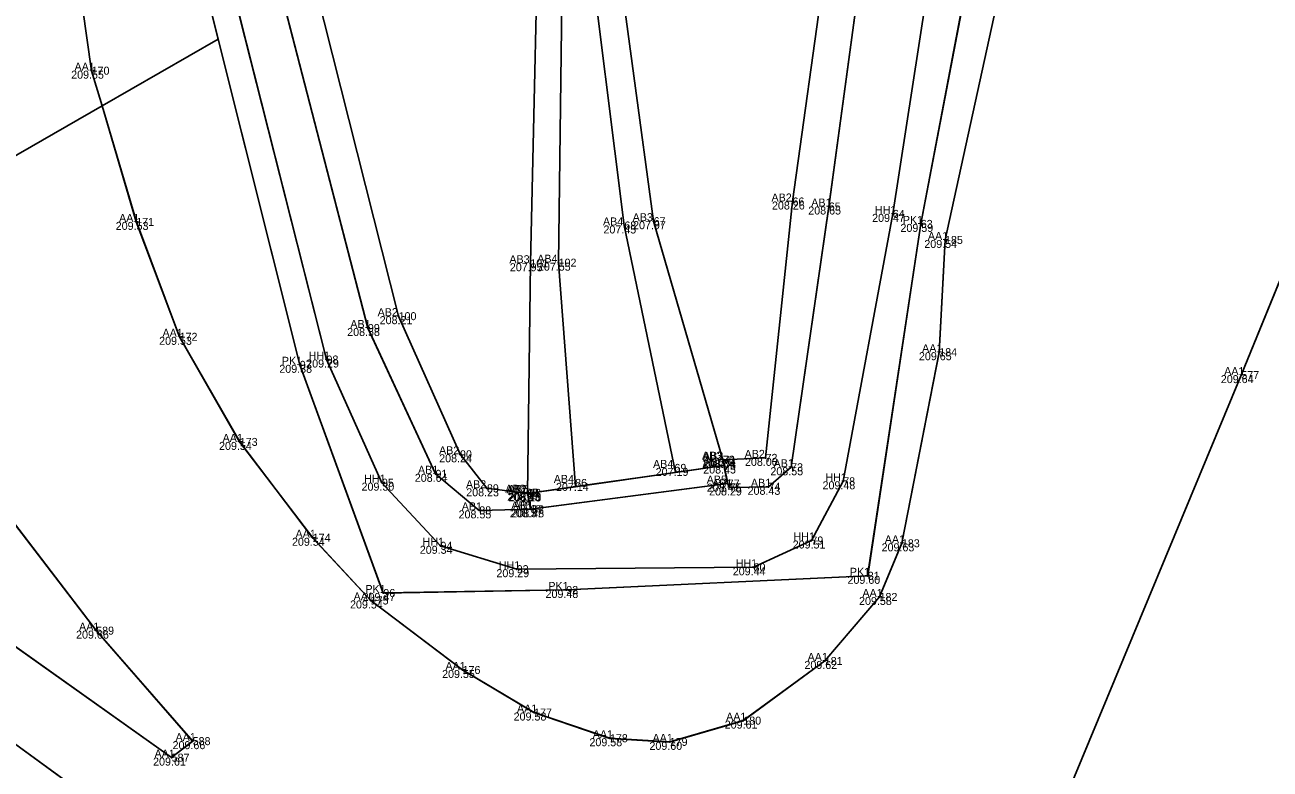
# Model space of a CAD drawing. Extents: x -262982 to -262706, y -1238714 to -1237093.
# Drawn here: x -262957.98 to -262926.85, y -1238394.45 to -1238375.85 of the extents above; entities that cross this region are included whole.
import ezdxf

# ---------------------------------------------------------------- set-up
doc = ezdxf.new("R2010")
doc.units = 0
for name, color, linetype in [('01_Hrana_betónu', 7, 'Continuous'), ('02_Oplotenie', 7, 'Continuous'), ('03_Asfalt', 7, 'Continuous'), ('05_Hrana_terénu', 7, 'Continuous'), ('07_Iné', 7, 'Continuous'), ('10', 7, 'Continuous'), ('Groma (21)', 7, 'Continuous'), ('Groma (22)', 7, 'Continuous'), ('Groma (23)', 7, 'Continuous'), ('Groma (24)', 7, 'Continuous'), ('U001_Zeleň_mimo', 7, 'Continuous'), ('U002_Asfalt', 7, 'Continuous'), ('U002_Betónové panely', 7, 'Continuous'), ('U002_Betóny_prídavné', 7, 'Continuous'), ('U002_Zeleň_mimo', 7, 'Continuous'), ('U002_Zeleň_vnútro', 7, 'Continuous'), ('U002_Zeleň_zatrávňovač', 7, 'Continuous')]:
    doc.layers.add(name, color=color, linetype=linetype)

msp = doc.modelspace()

# ---------------------------------------------------------------- linework, layer by layer
at = {"layer": '01_Hrana_betónu'}
for points in [[(-262944.213, -1238387.387), (-262944.634, -1238381.789), (-262944.5, -1238371.343), (-262941.2, -1238360.927), (-262935.086, -1238341.218), (-262927.632, -1238317.179), (-262920.793, -1238295.265), (-262911.171, -1238262.813), (-262915.352, -1238261.064), (-262915.337, -1238259.329), (-262909.866, -1238261.629), (-262904.904, -1238263.716)], [(-262916.095, -1238261.519), (-262911.974, -1238263.293), (-262921.591, -1238294.909), (-262928.534, -1238317.073), (-262935.896, -1238340.99), (-262941.971, -1238360.685), (-262945.096, -1238371.115), (-262945.34, -1238381.803), (-262945.412, -1238387.557)], [(-262941.714, -1238387.032), (-262942.991, -1238380.859), (-262943.934, -1238373.35), (-262940.485, -1238361.041), (-262934.456, -1238341.421), (-262927.277, -1238318.134), (-262920.116, -1238294.802), (-262913.64, -1238273.614), (-262910.214, -1238263.245), (-262905.769, -1238265.099), (-262904.904, -1238263.716)], [(-262905.769, -1238265.099), (-262909.81, -1238264.181), (-262912.956, -1238273.861), (-262919.396, -1238295.066), (-262926.538, -1238318.409), (-262933.693, -1238341.579), (-262939.683, -1238361.151), (-262943.246, -1238373.477), (-262942.259, -1238380.752), (-262940.526, -1238386.713)], [(-262905.769, -1238265.099), (-262909.014, -1238275.12), (-262915.393, -1238296.189), (-262922.597, -1238319.497), (-262929.796, -1238342.936), (-262935.083, -1238362.17), (-262937.995, -1238374.567), (-262938.788, -1238380.26), (-262939.46, -1238386.668), (-262940.526, -1238386.713), (-262940.498, -1238386.859)], [(-262940.36, -1238387.407), (-262939.388, -1238387.391), (-262938.822, -1238386.902), (-262937.88, -1238380.385), (-262937.119, -1238374.802), (-262934.23, -1238362.39), (-262928.952, -1238343.2), (-262921.717, -1238319.813), (-262915.107, -1238298.192), (-262908.208, -1238275.423), (-262904.855, -1238265.436)], [(-262945.333, -1238387.95), (-262946.617, -1238387.98), (-262947.712, -1238387.066), (-262949.402, -1238383.422), (-262952.187, -1238372.656), (-262952.759, -1238366.382)], [(-262951.91, -1238366.581), (-262951.321, -1238372.499), (-262948.634, -1238383.126), (-262947.098, -1238386.578), (-262946.426, -1238387.428), (-262945.412, -1238387.557)], [(-262945.333, -1238387.95), (-262945.412, -1238387.557), (-262944.213, -1238387.387), (-262941.714, -1238387.032), (-262940.498, -1238386.859), (-262940.407, -1238387.311), (-262940.36, -1238387.407)]]:
    msp.add_lwpolyline(points, dxfattribs=at)
at = {"layer": '02_Oplotenie'}
msp.add_lwpolyline([(-262939.39, -1238320.83), (-262941.19, -1238324.79), (-262946.68, -1238336.9), (-262951.035, -1238350.68), (-262953.195, -1238358.97), (-262953.815, -1238358.809), (-262955.312, -1238364.513), (-262954.553, -1238364.724), (-262954.681, -1238366.785), (-262954.024, -1238372.698), (-262953.142, -1238376.2), (-262951.104, -1238384.342), (-262949.016, -1238390.045), (-262944.443, -1238389.969), (-262936.906, -1238389.616), (-262935.581, -1238380.82), (-262934.566, -1238375.513), (-262931.812, -1238363.194), (-262926.159, -1238344.076), (-262918.903, -1238320.384), (-262912.242, -1238298.942), (-262905.326, -1238276.054), (-262902.598, -1238266.292), (-262902.107, -1238264.892)], dxfattribs=at)
at = {"layer": '03_Asfalt'}
for points in [[(-262929.61, -1238361.054), (-262931.199, -1238364.162), (-262933.003, -1238372.216), (-262934.974, -1238381.221), (-262935.119, -1238384.027), (-262936.052, -1238388.803), (-262936.611, -1238390.144), (-262937.981, -1238391.744), (-262940.017, -1238393.235), (-262941.857, -1238393.766), (-262943.351, -1238393.675), (-262945.246, -1238393.033), (-262947.034, -1238391.969), (-262949.331, -1238390.232), (-262950.782, -1238388.665), (-262952.605, -1238386.269), (-262954.108, -1238383.642), (-262955.193, -1238380.77), (-262956.048, -1238377.869), (-262956.307, -1238376.99), (-262956.874, -1238372.978), (-262956.554, -1238367.788), (-262955.999, -1238364.917), (-262954.725, -1238360.416)], [(-262931.78, -1238394.73), (-262927.567, -1238384.599), (-262924.973, -1238378.239), (-262922.576, -1238372.621), (-262920.572, -1238369.785), (-262920.498, -1238369.428)], [(-262967.893, -1238384.386), (-262961.125, -1238389.323), (-262954.307, -1238394.16), (-262953.782, -1238393.748), (-262956.194, -1238390.986), (-262959.165, -1238387.112), (-262961.145, -1238384.138), (-262962.629, -1238381.652), (-262966.72, -1238383.885)], [(-262954.673, -1238396.412), (-262962.054, -1238391.026), (-262968.907, -1238386.238), (-262974.83, -1238389.493)]]:
    msp.add_lwpolyline(points, dxfattribs=at)
at = {"layer": '05_Hrana_terénu'}
msp.add_lwpolyline([(-262920.126, -1238320.151), (-262927.385, -1238343.686), (-262932.704, -1238362.854), (-262935.453, -1238375.219), (-262936.279, -1238380.57), (-262937.519, -1238387.253), (-262938.314, -1238388.733), (-262939.759, -1238389.403), (-262945.681, -1238389.45), (-262947.587, -1238388.865), (-262949.049, -1238387.288), (-262950.436, -1238384.21), (-262953.347, -1238372.702), (-262953.777, -1238366.63), (-262954.163, -1238366.041), (-262952.487, -1238358.01), (-262951.855, -1238357.25), (-262949.897, -1238349.853), (-262950.29, -1238348.92), (-262949.45, -1238345.83), (-262948.76, -1238345.496), (-262946.63, -1238339.15), (-262945.04, -1238334.12), (-262941.75, -1238326.63)], dxfattribs=at)
at = {"layer": '07_Iné'}
msp.add_lwpolyline([(-262940.407, -1238387.311), (-262940.498, -1238386.859), (-262945.412, -1238387.557), (-262945.334, -1238387.946)], close=True, dxfattribs=at)
at = {"layer": '10'}
msp.add_lwpolyline([(-262982.434, -1238375.977), (-262968.907, -1238386.238), (-262962.054, -1238391.026), (-262954.673, -1238396.412), (-262941.774, -1238405.784), (-262928.896, -1238415.327), (-262917.716, -1238423.993), (-262905.824, -1238433.621), (-262895.067, -1238441.663), (-262870.407, -1238460.6)], dxfattribs=at)
at = {"layer": 'Groma (21)'}
for centre in [(-262956.307, -1238376.99), (-262938.788, -1238380.26), (-262937.88, -1238380.385), (-262936.279, -1238380.57), (-262955.193, -1238380.77), (-262942.991, -1238380.859), (-262942.259, -1238380.752), (-262935.581, -1238380.82), (-262934.974, -1238381.221), (-262945.34, -1238381.803), (-262944.634, -1238381.789), (-262948.634, -1238383.126), (-262949.402, -1238383.422), (-262954.108, -1238383.642), (-262935.119, -1238384.027), (-262951.104, -1238384.342), (-262950.436, -1238384.21), (-262927.567, -1238384.599), (-262952.605, -1238386.269), (-262947.098, -1238386.578), (-262940.526, -1238386.713), (-262940.499, -1238386.717), (-262940.498, -1238386.859), (-262939.46, -1238386.668), (-262938.822, -1238386.902), (-262947.712, -1238387.066), (-262941.738, -1238386.918), (-262949.049, -1238387.288), (-262946.426, -1238387.428), (-262944.22, -1238387.294), (-262940.407, -1238387.311), (-262940.36, -1238387.407), (-262939.388, -1238387.391), (-262937.519, -1238387.253), (-262945.444, -1238387.54), (-262945.412, -1238387.557), (-262945.37, -1238387.544), (-262946.617, -1238387.98), (-262945.333, -1238387.95), (-262945.294, -1238387.955), (-262950.782, -1238388.665), (-262938.314, -1238388.733), (-262947.587, -1238388.865), (-262936.052, -1238388.803), (-262939.759, -1238389.403), (-262945.681, -1238389.45), (-262936.906, -1238389.616), (-262944.443, -1238389.969), (-262949.331, -1238390.232), (-262949.016, -1238390.045), (-262936.611, -1238390.144), (-262956.194, -1238390.986), (-262937.981, -1238391.744), (-262947.034, -1238391.969), (-262945.246, -1238393.033), (-262940.017, -1238393.235), (-262953.782, -1238393.748), (-262943.351, -1238393.675), (-262941.857, -1238393.766), (-262954.307, -1238394.16)]:
    msp.add_circle(centre, 0.01, dxfattribs=at)
at = {"layer": 'U001_Zeleň_mimo'}
msp.add_lwpolyline([(-262966.43, -1238405.69), (-262974.83, -1238389.49), (-262968.91, -1238386.24), (-262962.05, -1238391.03), (-262954.67, -1238396.41)], dxfattribs=at)
msp.add_lwpolyline([(-262966.43, -1238405.69), (-262974.83, -1238389.49), (-262968.91, -1238386.24), (-262962.05, -1238391.03), (-262954.67, -1238396.41)], dxfattribs=at)
at = {"layer": 'U002_Asfalt'}
for points in [[(-262926.72, -1238350.73), (-262915.49, -1238369.52), (-262916.65, -1238369.25), (-262918.3, -1238369.33), (-262920.5, -1238369.43), (-262920.57, -1238369.78), (-262922.58, -1238372.62), (-262924.97, -1238378.24), (-262927.57, -1238384.6), (-262931.78, -1238394.73)], [(-262962.63, -1238381.65), (-262956.048, -1238377.869), (-262955.19, -1238380.77), (-262954.11, -1238383.64), (-262952.61, -1238386.27), (-262950.78, -1238388.67), (-262949.33, -1238390.23), (-262947.03, -1238391.97), (-262945.25, -1238393.03), (-262943.35, -1238393.68), (-262941.86, -1238393.77), (-262940.02, -1238393.24), (-262937.98, -1238391.74), (-262936.61, -1238390.14), (-262936.05, -1238388.8), (-262935.12, -1238384.03), (-262934.97, -1238381.22), (-262933, -1238372.22), (-262931.2, -1238364.16), (-262929.61, -1238361.05)], [(-262961.13, -1238389.32), (-262954.31, -1238394.16), (-262953.78, -1238393.75), (-262956.19, -1238390.99), (-262959.16, -1238387.11)], [(-262954.67, -1238396.41), (-262962.05, -1238391.03)]]:
    msp.add_lwpolyline(points, dxfattribs=at)
at = {"layer": 'U002_Betónové panely'}
msp.add_lwpolyline([(-262928.95, -1238343.2), (-262934.23, -1238362.39), (-262937.12, -1238374.8), (-262937.88, -1238380.39), (-262938.82, -1238386.9), (-262939.39, -1238387.39), (-262940.36, -1238387.41), (-262940.41, -1238387.31), (-262940.5, -1238386.86), (-262941.71, -1238387.03), (-262944.21, -1238387.39), (-262945.41, -1238387.56), (-262945.33, -1238387.95), (-262946.62, -1238387.98), (-262947.71, -1238387.07), (-262949.4, -1238383.42), (-262952.19, -1238372.66), (-262952.76, -1238366.38), (-262951.91, -1238366.58), (-262950.1, -1238358.54)], dxfattribs=at)
at = {"layer": 'U002_Betóny_prídavné'}
msp.add_lwpolyline([(-262940.5, -1238386.86), (-262940.41, -1238387.31), (-262945.33, -1238387.95), (-262945.41, -1238387.56)], close=True, dxfattribs=at)
at = {"layer": 'U002_Zeleň_mimo'}
for points in [[(-262931.78, -1238394.73), (-262927.57, -1238384.6), (-262924.97, -1238378.24), (-262922.58, -1238372.62), (-262920.5, -1238369.43), (-262918.3, -1238369.33), (-262916.65, -1238369.25), (-262915.49, -1238369.52), (-262914.76, -1238370.7), (-262914.55, -1238372.02), (-262914.27, -1238382.69), (-262914.16, -1238387.19), (-262913.44, -1238391.68), (-262911.99, -1238397.34)], [(-262933, -1238372.22), (-262934.97, -1238381.22), (-262935.12, -1238384.03), (-262936.05, -1238388.8), (-262936.61, -1238390.14), (-262937.98, -1238391.74), (-262940.02, -1238393.24), (-262941.86, -1238393.77), (-262943.35, -1238393.68), (-262945.25, -1238393.03), (-262947.03, -1238391.97), (-262949.33, -1238390.23), (-262950.78, -1238388.67), (-262952.61, -1238386.27), (-262954.11, -1238383.64), (-262955.19, -1238380.77), (-262956.048, -1238377.869), (-262953.142, -1238376.2), (-262951.1, -1238384.34), (-262949.02, -1238390.05), (-262944.44, -1238389.97), (-262936.91, -1238389.62), (-262935.58, -1238380.82), (-262934.57, -1238375.51)]]:
    msp.add_lwpolyline(points, dxfattribs=at)
msp.add_lwpolyline([(-262961.15, -1238384.14), (-262959.16, -1238387.11), (-262956.19, -1238390.99), (-262953.78, -1238393.75), (-262954.31, -1238394.16), (-262961.13, -1238389.32), (-262967.89, -1238384.39), (-262966.72, -1238383.89), (-262962.63, -1238381.65)], close=True, dxfattribs=at)
at = {"layer": 'U002_Zeleň_vnútro'}
for points in [[(-262918.9, -1238320.38), (-262926.16, -1238344.08), (-262931.81, -1238363.19), (-262934.57, -1238375.51), (-262935.58, -1238380.82), (-262936.91, -1238389.62), (-262944.44, -1238389.97), (-262949.02, -1238390.05), (-262951.1, -1238384.34), (-262954.02, -1238372.7), (-262954.68, -1238366.78), (-262954.55, -1238364.72), (-262953.2, -1238358.97), (-262951.03, -1238350.68), (-262946.68, -1238336.9), (-262941.19, -1238324.79)], [(-262952.49, -1238358.01), (-262954.16, -1238366.04), (-262953.78, -1238366.63), (-262953.35, -1238372.7), (-262950.44, -1238384.21), (-262949.05, -1238387.29), (-262947.59, -1238388.87), (-262945.68, -1238389.45), (-262939.76, -1238389.4), (-262938.31, -1238388.73), (-262937.52, -1238387.25), (-262936.28, -1238380.57), (-262935.45, -1238375.22), (-262932.7, -1238362.85), (-262927.39, -1238343.69)]]:
    msp.add_lwpolyline(points, dxfattribs=at)
at = {"layer": 'U002_Zeleň_zatrávňovač'}
for points in [[(-262935.45, -1238375.22), (-262936.28, -1238380.57), (-262937.52, -1238387.25), (-262938.31, -1238388.73), (-262939.76, -1238389.4), (-262945.68, -1238389.45), (-262947.59, -1238388.87), (-262949.05, -1238387.29), (-262950.44, -1238384.21), (-262953.35, -1238372.7)], [(-262952.19, -1238372.66), (-262949.4, -1238383.42), (-262947.71, -1238387.07), (-262946.62, -1238387.98), (-262945.33, -1238387.95), (-262940.41, -1238387.31), (-262940.36, -1238387.41), (-262939.39, -1238387.39), (-262938.82, -1238386.9), (-262937.88, -1238380.39), (-262937.12, -1238374.8)]]:
    msp.add_lwpolyline(points, dxfattribs=at)

# ---------------------------------------------------------------- texts
at = {"layer": 'Groma (22)'}
for s, p in [('170', (-262956.307, -1238377.09)), ('66', (-262938.788, -1238380.36)), ('65', (-262937.88, -1238380.485)), ('171', (-262955.193, -1238380.87)), ('67', (-262942.259, -1238380.852)), ('64', (-262936.279, -1238380.67)), ('68', (-262942.991, -1238380.959)), ('63', (-262935.581, -1238380.92)), ('185', (-262934.974, -1238381.321)), ('101', (-262945.34, -1238381.903)), ('102', (-262944.634, -1238381.889)), ('100', (-262948.634, -1238383.226)), ('99', (-262949.402, -1238383.522)), ('172', (-262954.108, -1238383.742)), ('184', (-262935.119, -1238384.127)), ('97', (-262951.104, -1238384.442)), ('98', (-262950.436, -1238384.31)), ('577', (-262927.567, -1238384.699)), ('173', (-262952.605, -1238386.369)), ('90', (-262947.098, -1238386.678)), ('72', (-262939.46, -1238386.768)), ('69', (-262941.738, -1238387.018)), ('70', (-262940.526, -1238386.813)), ('71', (-262940.499, -1238386.817)), ('76', (-262940.498, -1238386.959)), ('73', (-262938.822, -1238387.002)), ('95', (-262949.049, -1238387.388)), ('91', (-262947.712, -1238387.166)), ('86', (-262944.22, -1238387.394)), ('77', (-262940.407, -1238387.411)), ('78', (-262937.519, -1238387.353)), ('89', (-262946.426, -1238387.528)), ('85', (-262945.444, -1238387.64)), ('84', (-262945.412, -1238387.657)), ('83', (-262945.37, -1238387.644)), ('75', (-262940.36, -1238387.507)), ('74', (-262939.388, -1238387.491)), ('88', (-262946.617, -1238388.08)), ('87', (-262945.333, -1238388.05)), ('82', (-262945.294, -1238388.055)), ('174', (-262950.782, -1238388.765)), ('94', (-262947.587, -1238388.965)), ('79', (-262938.314, -1238388.833)), ('183', (-262936.052, -1238388.903)), ('93', (-262945.681, -1238389.55)), ('80', (-262939.759, -1238389.503)), ('81', (-262936.906, -1238389.716)), ('96', (-262949.016, -1238390.145)), ('92', (-262944.443, -1238390.069)), ('175', (-262949.331, -1238390.332)), ('182', (-262936.611, -1238390.244)), ('589', (-262956.194, -1238391.086)), ('176', (-262947.034, -1238392.069)), ('181', (-262937.981, -1238391.844)), ('177', (-262945.246, -1238393.133)), ('180', (-262940.017, -1238393.335)), ('588', (-262953.782, -1238393.848)), ('178', (-262943.351, -1238393.775)), ('179', (-262941.857, -1238393.866)), ('587', (-262954.307, -1238394.26))]:
    msp.add_text(s, height=0.2, dxfattribs=at).set_placement(p)
at = {"layer": 'Groma (23)'}
for s, p in [('209.55', (-262956.819, -1238377.19)), ('208.26', (-262939.3, -1238380.46)), ('208.65', (-262938.392, -1238380.585)), ('209.47', (-262936.796, -1238380.77)), ('209.53', (-262955.705, -1238380.97)), ('207.45', (-262943.513, -1238381.059)), ('207.97', (-262942.772, -1238380.952)), ('209.59', (-262936.088, -1238381.02)), ('209.54', (-262935.491, -1238381.421)), ('207.95', (-262945.853, -1238382.003)), ('207.55', (-262945.151, -1238381.989)), ('208.21', (-262949.107, -1238383.326)), ('208.58', (-262949.919, -1238383.622)), ('209.53', (-262954.62, -1238383.842)), ('209.65', (-262935.626, -1238384.227)), ('209.38', (-262951.616, -1238384.542)), ('209.29', (-262950.943, -1238384.41)), ('209.64', (-262928.079, -1238384.799)), ('209.54', (-262953.122, -1238386.469)), ('208.24', (-262947.619, -1238386.778)), ('208.04', (-262941.046, -1238386.913)), ('208.04', (-262941.019, -1238386.917)), ('208.45', (-262941.019, -1238387.059)), ('208.00', (-262939.975, -1238386.868)), ('208.55', (-262939.339, -1238387.102)), ('208.64', (-262948.229, -1238387.266)), ('207.19', (-262942.207, -1238387.118)), ('209.30', (-262949.56, -1238387.488)), ('208.23', (-262946.943, -1238387.628)), ('207.14', (-262944.699, -1238387.494)), ('208.47', (-262940.929, -1238387.511)), ('208.29', (-262940.872, -1238387.607)), ('208.43', (-262939.909, -1238387.591)), ('209.48', (-262938.036, -1238387.453)), ('208.13', (-262945.917, -1238387.74)), ('208.40', (-262945.89, -1238387.744)), ('208.15', (-262945.885, -1238387.757)), ('208.55', (-262947.134, -1238388.18)), ('208.37', (-262945.85, -1238388.15)), ('208.43', (-262945.815, -1238388.155)), ('209.54', (-262951.299, -1238388.865)), ('209.51', (-262938.782, -1238388.933)), ('209.34', (-262948.104, -1238389.065)), ('209.63', (-262936.559, -1238389.003)), ('209.29', (-262946.188, -1238389.65)), ('209.44', (-262940.28, -1238389.603)), ('209.60', (-262937.412, -1238389.816)), ('209.48', (-262944.96, -1238390.169)), ('209.54', (-262949.848, -1238390.432)), ('209.47', (-262949.533, -1238390.245)), ('209.58', (-262937.123, -1238390.344)), ('209.66', (-262956.696, -1238391.186)), ('209.62', (-262938.488, -1238391.944)), ('209.55', (-262947.546, -1238392.169)), ('209.58', (-262945.758, -1238393.233)), ('209.61', (-262940.481, -1238393.435)), ('209.66', (-262954.284, -1238393.948)), ('209.58', (-262943.863, -1238393.875)), ('209.60', (-262942.363, -1238393.966)), ('209.61', (-262954.771, -1238394.36))]:
    msp.add_text(s, height=0.2, dxfattribs=at).set_placement(p)
at = {"layer": 'Groma (24)'}
for s, p in [('AA1', (-262956.735, -1238376.99)), ('AB2', (-262939.312, -1238380.26)), ('AB1', (-262938.318, -1238380.385)), ('AA1', (-262955.621, -1238380.77)), ('AB4', (-262943.525, -1238380.859)), ('AB3', (-262942.783, -1238380.752)), ('HH1', (-262936.726, -1238380.57)), ('PK1', (-262936.028, -1238380.82)), ('AA1', (-262935.402, -1238381.221)), ('AB3', (-262945.864, -1238381.803)), ('AB4', (-262945.168, -1238381.789)), ('AB2', (-262949.158, -1238383.126)), ('AA1', (-262954.536, -1238383.642)), ('AB1', (-262949.84, -1238383.422)), ('HH1', (-262950.883, -1238384.21)), ('AA1', (-262935.547, -1238384.027)), ('PK1', (-262951.551, -1238384.342)), ('AA1', (-262927.995, -1238384.599)), ('AA1', (-262953.033, -1238386.269)), ('AB2', (-262947.622, -1238386.578)), ('AB3', (-262941.05, -1238386.713)), ('AB2', (-262941.023, -1238386.717)), ('AB2', (-262939.984, -1238386.668)), ('AB1', (-262948.15, -1238387.066)), ('AB4', (-262942.272, -1238386.918)), ('AB5', (-262941.022, -1238386.859)), ('AB1', (-262939.26, -1238386.902)), ('HH1', (-262949.496, -1238387.288)), ('AB4', (-262944.754, -1238387.294)), ('AB5', (-262940.931, -1238387.311)), ('AB1', (-262940.798, -1238387.407)), ('AB1', (-262939.826, -1238387.391)), ('HH1', (-262937.966, -1238387.253)), ('AB2', (-262946.95, -1238387.428)), ('AB3', (-262945.968, -1238387.54)), ('AB2', (-262945.936, -1238387.557)), ('AB5', (-262945.894, -1238387.544)), ('AB1', (-262947.055, -1238387.98)), ('AB5', (-262945.818, -1238387.955)), ('AB1', (-262945.771, -1238387.95)), ('AA1', (-262951.21, -1238388.665)), ('HH1', (-262948.034, -1238388.865)), ('HH1', (-262938.761, -1238388.733)), ('AA1', (-262936.48, -1238388.803)), ('HH1', (-262946.128, -1238389.45)), ('HH1', (-262940.206, -1238389.403)), ('PK1', (-262937.353, -1238389.616)), ('PK1', (-262949.463, -1238390.045)), ('PK1', (-262944.89, -1238389.969)), ('AA1', (-262937.039, -1238390.144)), ('AA1', (-262949.759, -1238390.232)), ('AA1', (-262956.622, -1238390.986)), ('AA1', (-262938.409, -1238391.744)), ('AA1', (-262947.462, -1238391.969)), ('AA1', (-262945.674, -1238393.033)), ('AA1', (-262940.445, -1238393.235)), ('AA1', (-262954.21, -1238393.748)), ('AA1', (-262943.779, -1238393.675)), ('AA1', (-262942.285, -1238393.766)), ('AA1', (-262954.735, -1238394.16))]:
    msp.add_text(s, height=0.2, dxfattribs=at).set_placement(p)

doc.saveas('drawing.dxf')
